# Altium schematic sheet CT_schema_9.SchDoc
size 274 x 160 mm
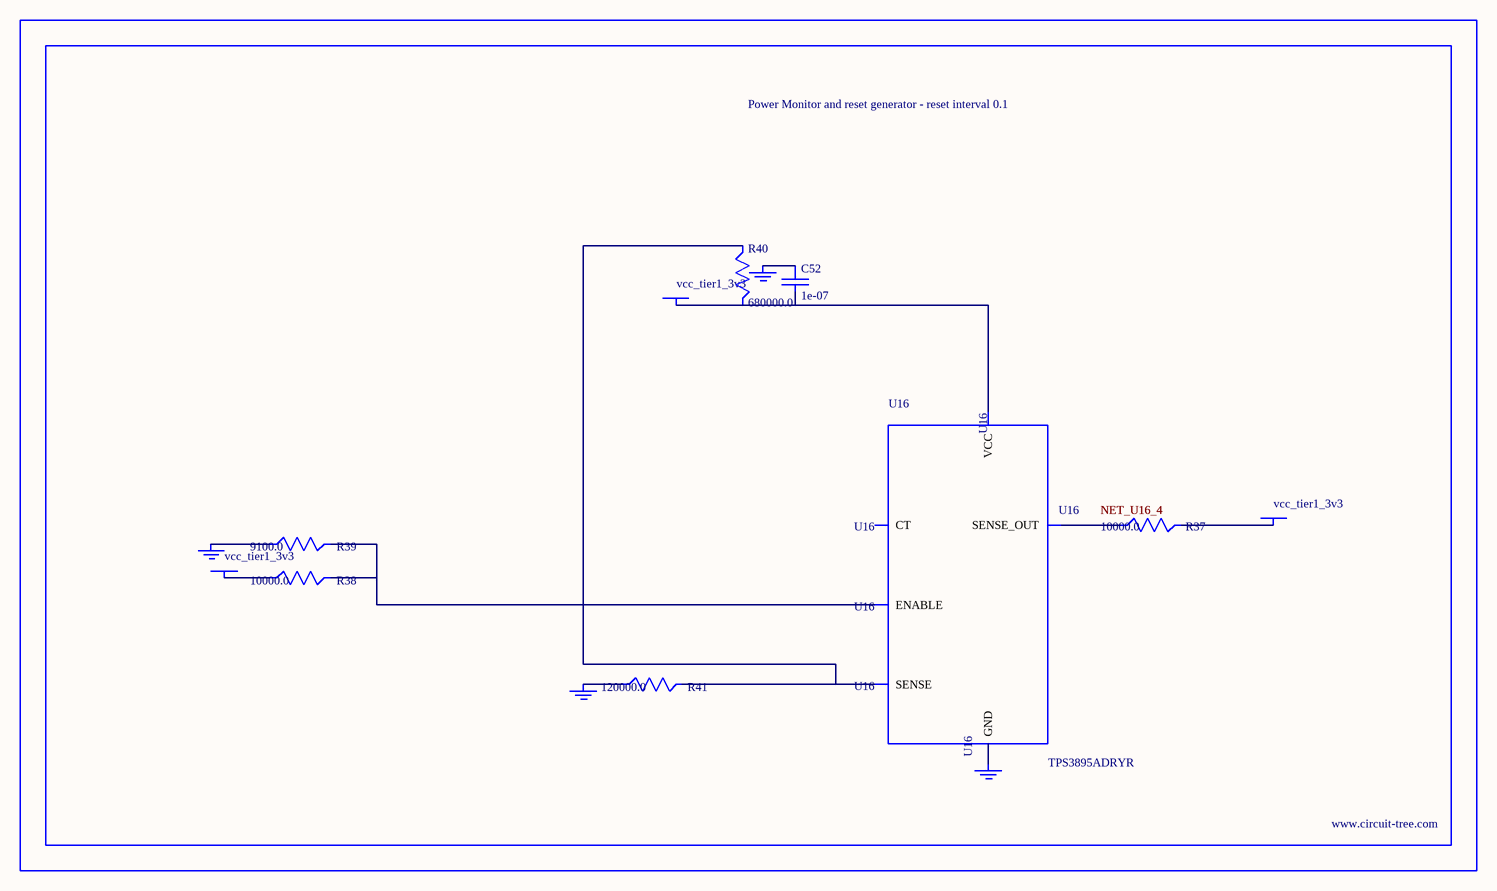
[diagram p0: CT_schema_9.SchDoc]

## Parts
BORDER8  (no value)
C52  1e-07  [C0402]
GND_INSTANCE_8_0  (no value)
GND_INSTANCE_8_1  (no value)
GND_INSTANCE_8_2  (no value)
GND_INSTANCE_8_3  (no value)
POWER_INSTANCE_8_0  vcc_tier1_3v3
POWER_INSTANCE_8_1  vcc_tier1_3v3
POWER_INSTANCE_8_2  vcc_tier1_3v3
R37  10000.0  [R0603]
R38  10000.0  [R0603]
R39  9100.0  [R0603]
R40  680000.0  [R0603]
R41  120000.0  [R0603]
U16  TPS3895ADRYR  [SON-6]

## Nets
NetC52_1: C52.1 GND_INSTANCE_8_2.0(GND)
NetC52_2: C52.2 POWER_INSTANCE_8_2.0(PWR) R40.2 U16.6(VCC)
NetGND_INSTANCE_8_0_0: GND_INSTANCE_8_0.0(GND) R39.1
NetGND_INSTANCE_8_1_0: GND_INSTANCE_8_1.0(GND) R41.1
NetGND_INSTANCE_8_3_0: GND_INSTANCE_8_3.0(GND) U16.2(GND)
NetPOWER_INSTANCE_8_0_0: POWER_INSTANCE_8_0.0(PWR) R38.1
NetPOWER_INSTANCE_8_1_0: POWER_INSTANCE_8_1.0(PWR) R37.2
NetR37_1: R37.1 U16.4(SENSE_OUT)
NetR38_2: R38.2 R39.2 U16.1(ENABLE)
NetR40_1: R40.1 R41.2 U16.3(SENSE)

Not connected (* = marked no-connect by the designer): U16 5(CT)

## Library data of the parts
BORDER8 = BORDER_PAGE8
C52 = C0402C104K3RACTU
GND_INSTANCE_8_0-GND_INSTANCE_8_3 = GND
POWER_INSTANCE_8_0-POWER_INSTANCE_8_2 = PWR
R37 R38 = RC0603JR-0710KL
R39 = RC0603JR-079K1L
R40 = RC0603JR-07680KL
R41 = RC0603JR-07120KL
